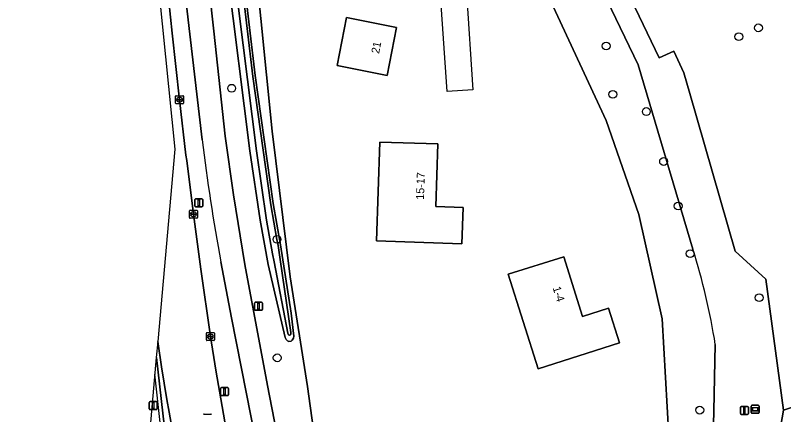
# Model space of a CAD drawing. Extents: x 159451 to 160664, y 388402 to 389723.
# Drawn here: x 159456.5 to 159552.4, y 389143.7 to 389193.6 of the extents above; entities that cross this region are included whole.
import ezdxf

# ---------------------------------------------------------------- set-up
doc = ezdxf.new("R2010")
doc.units = 0
for name, color, linetype in [('IMGEO_Afsluitpaal', 7, 'Continuous'), ('IMGEO_Berm_groen', 7, 'Continuous'), ('IMGEO_Boom', 7, 'Continuous'), ('IMGEO_Bouwland', 7, 'Continuous'), ('IMGEO_Fietspad_gesloten', 7, 'Continuous'), ('IMGEO_Grasland_overig', 7, 'Continuous'), ('IMGEO_Greppel_droge_sloot', 7, 'Continuous'), ('IMGEO_Groenvoorziening', 7, 'Continuous'), ('IMGEO_Hek', 7, 'Continuous'), ('IMGEO_Informatiebord', 7, 'Continuous'), ('IMGEO_Kolk', 7, 'Continuous'), ('IMGEO_Lichtmast', 7, 'Continuous'), ('IMGEO_Oever', 7, 'Continuous'), ('IMGEO_Pand', 7, 'Continuous'), ('IMGEO_Pand_nummerreeks', 7, 'Continuous'), ('IMGEO_Pand_vergunning_verleend', 7, 'Continuous'), ('IMGEO_Rijbaan_regionaal_gesloten', 7, 'Continuous'), ('IMGEO_Rioolput', 7, 'Continuous'), ('IMGEO_Voetpad_open', 7, 'Continuous')]:
    doc.layers.add(name, color=color, linetype=linetype)

msp = doc.modelspace()

# ---------------------------------------------------------------- linework, layer by layer
at = {"layer": 'IMGEO_Afsluitpaal'}
for p, q in [((159547.004, 389143.85), (159547.004, 389144.65)), ((159547.004, 389144.65), (159547.004, 389143.85)), ((159547.104, 389144.75), (159547.894, 389144.75)), ((159547.894, 389144.75), (159547.104, 389144.75)), ((159547.994, 389144.65), (159547.994, 389143.85)), ((159547.994, 389143.85), (159547.994, 389144.65)), ((159547.894, 389143.75), (159547.104, 389143.75)), ((159547.104, 389143.75), (159547.894, 389143.75))]:
    msp.add_line(p, q, dxfattribs=at)
msp.add_lwpolyline([(159547.424, 389144.625), (159547.574, 389144.625), (159547.574, 389143.875), (159547.424, 389143.875), (159547.424, 389144.625)], dxfattribs=at)
for centre, start, end in [((159547.104, 389144.65), 90, 180), ((159547.104, 389144.65), 90, 180), ((159547.894, 389144.65), 0, 90), ((159547.894, 389144.65), 360, 90), ((159547.104, 389143.85), 180, 270), ((159547.104, 389143.85), 180, 270), ((159547.894, 389143.85), 270, 0), ((159547.894, 389143.85), 270, 0)]:
    msp.add_arc(centre, 0.1, start, end, dxfattribs=at)
at = {"layer": 'IMGEO_Berm_groen'}
for points in [[(159479.81, 389178.066), (159478.244, 389191.231), (159476.688, 389204.954), (159476.115, 389210.723), (159473.293, 389238.955), (159471.683, 389255.143), (159470.151, 389272.51), (159468.609, 389291.384), (159467.063, 389310.472), (159465.649, 389329.916), (159464.342, 389348.5), (159462.508, 389376.402), (159461.071, 389403.687), (159459.294, 389436.93)], [(159475.213, 389199.409), (159476.055, 389191.357), (159476.981, 389183.062), (159477.784, 389176.125), (159477.869, 389175.45), (159478.713, 389168.759), (159479.637, 389161.877), (159480.832, 389153.482), (159481.503, 389149.299), (159483.264, 389139.262), (159485.702, 389125.061), (159486.085, 389122.792)], [(159489.673, 389123.332), (159487.529, 389135.114), (159485.311, 389146.532), (159483.459, 389155.81), (159482.145, 389162.815)], [(159474.251, 389152.87), (159474.073, 389150.873), (159474.122, 389150.878), (159477.483, 389121.203), (159479.117, 389121.427)], [(159479.49, 389121.919), (159477.882, 389131.561), (159476.254, 389140.727), (159475.679, 389144.041), (159475.404, 389145.63), (159474.719, 389149.681), (159474.251, 389152.87)]]:
    msp.add_lwpolyline(points, dxfattribs=at)
msp.add_arc((159698.001, 389203.668), 219.688, 186.6923, 190.71702, dxfattribs=at)
at = {"layer": 'IMGEO_Boom'}
for centre in [(159549.254, 389192.032), (159546.8, 389190.929), (159530.24, 389189.771), (159483.48, 389184.488), (159531.071, 389183.726), (159535.251, 389181.578), (159537.411, 389175.343), (159539.233, 389169.779), (159489.139, 389165.616), (159540.731, 389163.833), (159549.348, 389158.333), (159489.173, 389150.822), (159541.926, 389144.291)]:
    msp.add_circle(centre, 0.489, dxfattribs=at)
at = {"layer": 'IMGEO_Bouwland'}
msp.add_lwpolyline([(159486.712, 389292.863), (159536.847, 389188.304), (159538.67, 389189.107), (159539.945, 389186.409), (159540.689, 389183.824), (159546.355, 389164.126), (159550.196, 389160.656), (159552.375, 389144.269), (159583.383, 389154.602)], dxfattribs=at)
for points in [[(159487.441, 389272.575), (159480.836, 389288.81), (159478.228, 389288.738), (159479.211, 389271.897), (159488.551, 389179.124), (159490.78, 389160.929), (159492.959, 389147.253), (159495.943, 389125.547), (159496.063, 389124.735), (159496.335, 389123.276), (159496.729, 389122.189), (159497.183, 389121.597), (159498.11, 389121.139), (159499.541, 389121.106), (159518.516, 389121.775), (159539.156, 389122.203), (159538.081, 389141.023), (159537.243, 389155.693), (159534.303, 389168.702), (159530.224, 389180.456)], [(159504.064, 389192.091), (159502.892, 389186.087), (159496.658, 389187.324), (159497.826, 389193.308)], [(159509.239, 389177.532), (159508.962, 389169.711), (159512.369, 389169.587), (159512.206, 389165.051), (159501.559, 389165.416), (159501.991, 389177.773)], [(159518.017, 389161.253), (159524.936, 389163.454), (159527.305, 389155.997), (159530.546, 389157.029), (159531.919, 389152.7), (159521.761, 389149.463)]]:
    msp.add_lwpolyline(points, close=True, dxfattribs=at)
at = {"layer": 'IMGEO_Fietspad_gesloten'}
for points in [[(159461.071, 389403.687), (159462.508, 389376.402), (159464.342, 389348.5), (159465.649, 389329.916), (159467.063, 389310.472), (159468.609, 389291.384), (159470.151, 389272.51), (159471.683, 389255.143), (159473.293, 389238.955), (159476.115, 389210.723), (159476.688, 389204.954), (159478.244, 389191.231), (159479.81, 389178.066)], [(159482.145, 389162.815), (159483.459, 389155.81), (159485.311, 389146.532), (159487.529, 389135.114), (159489.673, 389123.332), (159492.885, 389123.261), (159492.482, 389125.078), (159491.057, 389131.504), (159487.963, 389147.366), (159485.138, 389162.462), (159483.697, 389171.161), (159482.691, 389178.486), (159481.255, 389191.613), (159479.595, 389206.774)]]:
    msp.add_lwpolyline(points, dxfattribs=at)
msp.add_arc((159698.001, 389203.668), 219.688, 186.6923, 190.71702, dxfattribs=at)
at = {"layer": 'IMGEO_Grasland_overig'}
for points in [[(159486.712, 389292.863), (159483.087, 389292.351), (159491.324, 389276.977), (159493.1, 389273.212), (159500, 389258.58), (159504.093, 389250), (159534.245, 389187.399), (159541.062, 389164.374)], [(159543.868, 389152.492), (159543.663, 389144.191), (159543.127, 389122.477), (159551.705, 389123.07), (159550.85, 389135.446), (159552.375, 389144.269), (159550.196, 389160.656), (159546.355, 389164.126), (159540.689, 389183.824), (159539.945, 389186.409), (159538.67, 389189.107), (159536.847, 389188.304), (159486.712, 389292.863)]]:
    msp.add_lwpolyline(points, dxfattribs=at)
msp.add_arc((159465.827, 389140.335), 78.982, 8.85455, 17.72, dxfattribs=at)
at = {"layer": 'IMGEO_Greppel_droge_sloot'}
msp.add_lwpolyline([(159483.778, 389198.834), (159486.574, 389176.685), (159487.854, 389168.014), (159488.602, 389163.826), (159488.797, 389162.797), (159490.487, 389153.895), (159490.538, 389153.785), (159490.596, 389153.695), (159490.701, 389153.64), (159490.759, 389153.652), (159490.843, 389153.709), (159490.882, 389153.795), (159490.884, 389153.895), (159490.866, 389154.004), (159489.544, 389163.12), (159489.298, 389164.837), (159489.139, 389165.616), (159488.368, 389169.95), (159486.114, 389185.938), (159483.986, 389203.971)], dxfattribs=at)
at = {"layer": 'IMGEO_Groenvoorziening'}
for points in [[(159471.882, 389288.893), (159473.199, 389272.868), (159474.73, 389255.582), (159476.315, 389239.166), (159479.167, 389211.269), (159479.595, 389206.774), (159481.255, 389191.613), (159482.691, 389178.486), (159483.697, 389171.161), (159485.138, 389162.462), (159487.963, 389147.366), (159491.057, 389131.504), (159492.482, 389125.078), (159495.943, 389125.547), (159492.959, 389147.253), (159490.78, 389160.929), (159488.551, 389179.124), (159479.211, 389271.897)], [(159541.062, 389164.374), (159534.245, 389187.399), (159504.093, 389250), (159500, 389258.58), (159493.1, 389273.212), (159487.441, 389272.575), (159530.224, 389180.456), (159534.303, 389168.702), (159537.243, 389155.693), (159538.081, 389141.023), (159539.156, 389122.203), (159543.127, 389122.477), (159543.663, 389144.191)], [(159484.285, 389204.106), (159486.412, 389186.084), (159488.663, 389170.113), (159489.602, 389164.953), (159490.896, 389156.395), (159491.245, 389153.512), (159491.194, 389153.27), (159491.057, 389153.021), (159490.9, 389152.917), (159490.624, 389152.875), (159490.458, 389152.949), (159490.295, 389153.124), (159490.153, 389153.348), (159488.037, 389162.469), (159487.05, 389167.999), (159485.767, 389176.684), (159482.97, 389198.843)], [(159583.383, 389154.602), (159552.375, 389144.269), (159550.85, 389135.446)], [(159543.663, 389144.191), (159543.868, 389152.492)]]:
    msp.add_lwpolyline(points, dxfattribs=at)
msp.add_arc((159465.827, 389140.335), 78.982, 8.85455, 17.72, dxfattribs=at)
at = {"layer": 'IMGEO_Hek'}
for points in [[(159552.375, 389144.269), (159583.383, 389154.602), (159594.464, 389157.944)], [(159474.61, 389142.37), (159473.885, 389148.761)]]:
    msp.add_lwpolyline(points, dxfattribs=at)
at = {"layer": 'IMGEO_Informatiebord'}
for p, q in [((159548.438, 389144.893), (159549.228, 389144.893)), ((159549.228, 389144.893), (159548.438, 389144.893)), ((159548.338, 389143.993), (159548.338, 389144.793)), ((159548.338, 389144.793), (159548.338, 389143.993)), ((159549.328, 389144.793), (159549.328, 389143.993)), ((159549.328, 389143.993), (159549.328, 389144.793)), ((159549.228, 389143.893), (159548.438, 389143.893)), ((159548.438, 389143.893), (159549.228, 389143.893))]:
    msp.add_line(p, q, dxfattribs=at)
for points in [[(159548.439, 389144.625), (159549.227, 389144.625), (159549.227, 389144.161), (159548.439, 389144.161), (159548.439, 389144.625)], [(159548.504, 389144.56), (159548.504, 389144.226), (159549.162, 389144.226), (159549.162, 389144.56), (159548.504, 389144.56)]]:
    msp.add_lwpolyline(points, dxfattribs=at)
for centre, start, end in [((159548.438, 389144.793), 90, 180), ((159548.438, 389144.793), 90, 180), ((159549.228, 389144.793), 0, 90), ((159549.228, 389144.793), 360, 90), ((159548.438, 389143.993), 180, 270), ((159548.438, 389143.993), 180, 270), ((159549.228, 389143.993), 270, 0), ((159549.228, 389143.993), 270, 0)]:
    msp.add_arc(centre, 0.1, start, end, dxfattribs=at)
at = {"layer": 'IMGEO_Kolk'}
for p, q in [((159476.48, 389182.636), (159476.48, 389183.488)), ((159476.555, 389183.562), (159477.407, 389183.562)), ((159476.968, 389183.342), (159476.993, 389183.342)), ((159477.481, 389183.488), (159477.481, 389182.636)), ((159477.407, 389182.562), (159476.555, 389182.562)), ((159476.739, 389183.056), (159476.739, 389183.068)), ((159477.177, 389183.019), (159476.779, 389183.019)), ((159476.782, 389183.105), (159477.18, 389183.105)), ((159476.991, 389182.782), (159476.966, 389182.782)), ((159477.223, 389183.068), (159477.223, 389183.056)), ((159478.212, 389168.333), (159478.212, 389169.185)), ((159478.287, 389169.259), (159479.139, 389169.259)), ((159478.7, 389169.039), (159478.725, 389169.039)), ((159479.213, 389169.185), (159479.213, 389168.333)), ((159479.139, 389168.259), (159478.287, 389168.259)), ((159478.471, 389168.753), (159478.471, 389168.765)), ((159478.909, 389168.716), (159478.511, 389168.716)), ((159478.514, 389168.802), (159478.912, 389168.802)), ((159478.723, 389168.479), (159478.698, 389168.479)), ((159478.955, 389168.765), (159478.955, 389168.753)), ((159480.331, 389153.056), (159480.331, 389153.908)), ((159480.406, 389153.982), (159481.258, 389153.982)), ((159480.633, 389153.525), (159481.031, 389153.525)), ((159480.819, 389153.762), (159480.844, 389153.762)), ((159481.332, 389153.908), (159481.332, 389153.056)), ((159481.258, 389152.982), (159480.406, 389152.982)), ((159480.59, 389153.476), (159480.59, 389153.488)), ((159481.028, 389153.439), (159480.63, 389153.439)), ((159480.842, 389153.202), (159480.817, 389153.202)), ((159481.074, 389153.488), (159481.074, 389153.476))]:
    msp.add_line(p, q, dxfattribs=at)
for points in [[(159476.48, 389182.636), (159476.48, 389183.488)], [(159476.555, 389183.562), (159477.407, 389183.562)], [(159477.481, 389183.488), (159477.481, 389182.636)], [(159477.407, 389182.562), (159476.555, 389182.562)], [(159478.212, 389168.333), (159478.212, 389169.185)], [(159478.287, 389169.259), (159479.139, 389169.259)], [(159479.213, 389169.185), (159479.213, 389168.333)], [(159479.139, 389168.259), (159478.287, 389168.259)], [(159480.331, 389153.056), (159480.331, 389153.908)], [(159480.406, 389153.982), (159481.258, 389153.982)], [(159481.332, 389153.908), (159481.332, 389153.056)], [(159481.258, 389152.982), (159480.406, 389152.982)]]:
    msp.add_lwpolyline(points, dxfattribs=at)
for centre, radius, start, end in [((159476.557, 389183.486), 0.0765, 91.55205, 178.44795), ((159476.557, 389183.486), 0.0765, 91.55205, 178.44795), ((159477.405, 389183.486), 0.0765, 1.55205, 88.44795), ((159477.405, 389183.486), 0.0765, 1.55205, 88.44795), ((159476.557, 389182.638), 0.0765, 181.55205, 268.44795), ((159476.557, 389182.638), 0.0765, 181.55205, 268.44795), ((159476.779, 389183.065), 0.0403, 85.87752, 175.75265), ((159476.776, 389183.055), 0.0366, 178.93798, 274.71019), ((159477.18, 389183.062), 0.043, 264.86636, 352.45326), ((159477.184, 389183.067), 0.0386, 1.73085, 96.63898), ((159477.405, 389182.638), 0.0765, 271.55205, 358.44795), ((159477.405, 389182.638), 0.0765, 271.55205, 358.44795), ((159478.289, 389169.183), 0.0765, 91.55205, 178.44795), ((159478.289, 389169.183), 0.0765, 91.55205, 178.44795), ((159479.137, 389169.183), 0.0765, 1.55205, 88.44795), ((159479.137, 389169.183), 0.0765, 1.55205, 88.44795), ((159478.289, 389168.335), 0.0765, 181.55205, 268.44795), ((159478.289, 389168.335), 0.0765, 181.55205, 268.44795), ((159478.511, 389168.762), 0.0403, 85.87752, 175.75265), ((159478.508, 389168.752), 0.0366, 178.93798, 274.71019), ((159478.912, 389168.759), 0.043, 264.86636, 352.45326), ((159478.916, 389168.764), 0.0386, 1.73085, 96.63898), ((159479.137, 389168.335), 0.0765, 271.55205, 358.44795), ((159479.137, 389168.335), 0.0765, 271.55205, 358.44795), ((159480.408, 389153.906), 0.0765, 91.55205, 178.44795), ((159480.408, 389153.906), 0.0765, 91.55205, 178.44795), ((159480.63, 389153.485), 0.0403, 85.87752, 175.75265), ((159481.035, 389153.487), 0.0386, 1.73085, 96.63898), ((159481.256, 389153.906), 0.0765, 1.55205, 88.44795), ((159481.256, 389153.906), 0.0765, 1.55205, 88.44795), ((159480.408, 389153.058), 0.0765, 181.55205, 268.44795), ((159480.408, 389153.058), 0.0765, 181.55205, 268.44795), ((159480.627, 389153.475), 0.0366, 178.93798, 274.71019), ((159481.031, 389153.482), 0.043, 264.86636, 352.45326), ((159481.256, 389153.058), 0.0765, 271.55205, 358.44795), ((159481.256, 389153.058), 0.0765, 271.55205, 358.44795)]:
    msp.add_arc(centre, radius, start, end, dxfattribs=at)
for centre, major_axis, ratio, start_param, end_param in [((159476.967, 389183.062), (-0.387, 0.002), 0.722429, 4.712389, 7.853982), ((159476.992, 389183.062), (-0.39, 0.002), 0.717154, 1.570796, 4.712389), ((159478.699, 389168.759), (-0.387, 0.002), 0.722429, 4.712389, 7.853982), ((159478.724, 389168.759), (-0.39, 0.002), 0.717154, 1.570796, 4.712389), ((159480.818, 389153.482), (-0.387, 0.002), 0.722429, 4.712389, 7.853982), ((159480.843, 389153.482), (-0.39, 0.002), 0.717154, 1.570796, 4.712389)]:
    msp.add_ellipse(centre, major_axis=major_axis, ratio=ratio, start_param=start_param, end_param=end_param, dxfattribs=at)
at = {"layer": 'IMGEO_Lichtmast'}
for p, q in [((159478.887, 389169.78), (159478.887, 389170.58)), ((159478.887, 389170.58), (159478.887, 389169.78)), ((159478.987, 389170.68), (159479.777, 389170.68)), ((159479.777, 389170.68), (159478.987, 389170.68)), ((159479.877, 389170.58), (159479.877, 389169.78)), ((159479.877, 389169.78), (159479.877, 389170.58)), ((159479.777, 389169.68), (159478.987, 389169.68)), ((159478.987, 389169.68), (159479.777, 389169.68)), ((159486.339, 389156.86), (159486.339, 389157.66)), ((159486.339, 389157.66), (159486.339, 389156.86)), ((159486.439, 389157.76), (159487.229, 389157.76)), ((159487.229, 389157.76), (159486.439, 389157.76)), ((159487.329, 389157.66), (159487.329, 389156.86)), ((159487.329, 389156.86), (159487.329, 389157.66)), ((159487.229, 389156.76), (159486.439, 389156.76)), ((159486.439, 389156.76), (159487.229, 389156.76)), ((159482.103, 389146.202), (159482.103, 389147.002)), ((159482.103, 389147.002), (159482.103, 389146.202)), ((159482.203, 389147.102), (159482.993, 389147.102)), ((159482.993, 389147.102), (159482.203, 389147.102)), ((159483.093, 389147.002), (159483.093, 389146.202)), ((159483.093, 389146.202), (159483.093, 389147.002)), ((159482.993, 389146.102), (159482.203, 389146.102)), ((159482.203, 389146.102), (159482.993, 389146.102)), ((159473.193, 389144.457), (159473.193, 389145.257)), ((159473.193, 389145.257), (159473.193, 389144.457)), ((159473.293, 389145.357), (159474.083, 389145.357)), ((159474.083, 389145.357), (159473.293, 389145.357)), ((159474.183, 389145.257), (159474.183, 389144.457)), ((159474.183, 389144.457), (159474.183, 389145.257)), ((159474.083, 389144.357), (159473.293, 389144.357)), ((159473.293, 389144.357), (159474.083, 389144.357))]:
    msp.add_line(p, q, dxfattribs=at)
for points in [[(159479.307, 389170.555), (159479.457, 389170.555), (159479.457, 389169.805), (159479.307, 389169.805), (159479.307, 389170.555)], [(159486.759, 389157.635), (159486.909, 389157.635), (159486.909, 389156.885), (159486.759, 389156.885), (159486.759, 389157.635)], [(159482.523, 389146.977), (159482.673, 389146.977), (159482.673, 389146.227), (159482.523, 389146.227), (159482.523, 389146.977)], [(159473.613, 389145.232), (159473.763, 389145.232), (159473.763, 389144.482), (159473.613, 389144.482), (159473.613, 389145.232)]]:
    msp.add_lwpolyline(points, dxfattribs=at)
for centre, start, end in [((159478.987, 389170.58), 90, 180), ((159478.987, 389170.58), 90, 180), ((159479.777, 389170.58), 0, 90), ((159479.777, 389170.58), 360, 90), ((159478.987, 389169.78), 180, 270), ((159478.987, 389169.78), 180, 270), ((159479.777, 389169.78), 270, 0), ((159479.777, 389169.78), 270, 0), ((159486.439, 389157.66), 90, 180), ((159486.439, 389157.66), 90, 180), ((159487.229, 389157.66), 0, 90), ((159487.229, 389157.66), 360, 90), ((159486.439, 389156.86), 180, 270), ((159486.439, 389156.86), 180, 270), ((159487.229, 389156.86), 270, 0), ((159487.229, 389156.86), 270, 0), ((159482.203, 389147.002), 90, 180), ((159482.203, 389147.002), 90, 180), ((159482.993, 389147.002), 0, 90), ((159482.993, 389147.002), 360, 90), ((159482.203, 389146.202), 180, 270), ((159482.203, 389146.202), 180, 270), ((159482.993, 389146.202), 270, 0), ((159482.993, 389146.202), 270, 0), ((159473.293, 389145.257), 90, 180), ((159473.293, 389145.257), 90, 180), ((159474.083, 389145.257), 0, 90), ((159474.083, 389145.257), 360, 90), ((159473.293, 389144.457), 180, 270), ((159473.293, 389144.457), 180, 270), ((159474.083, 389144.457), 270, 0), ((159474.083, 389144.457), 270, 0)]:
    msp.add_arc(centre, 0.1, start, end, dxfattribs=at)
at = {"layer": 'IMGEO_Oever'}
for points in [[(159482.97, 389198.843), (159485.767, 389176.684), (159487.05, 389167.999), (159488.037, 389162.469), (159490.153, 389153.348), (159490.295, 389153.124), (159490.458, 389152.949), (159490.624, 389152.875), (159490.9, 389152.917), (159491.057, 389153.021), (159491.194, 389153.27), (159491.245, 389153.512), (159490.896, 389156.395), (159489.602, 389164.953), (159488.663, 389170.113), (159486.412, 389186.084), (159484.285, 389204.106)], [(159483.986, 389203.971), (159486.114, 389185.938), (159488.368, 389169.95), (159489.139, 389165.616), (159489.298, 389164.837), (159489.544, 389163.12), (159490.866, 389154.004), (159490.884, 389153.895), (159490.882, 389153.795), (159490.843, 389153.709), (159490.759, 389153.652), (159490.701, 389153.64), (159490.596, 389153.695), (159490.538, 389153.785), (159490.487, 389153.895), (159488.797, 389162.797), (159488.602, 389163.826), (159487.854, 389168.014), (159486.574, 389176.685), (159483.778, 389198.834)]]:
    msp.add_lwpolyline(points, dxfattribs=at)
at = {"layer": 'IMGEO_Pand'}
for points in [[(159504.064, 389192.091), (159497.826, 389193.308), (159496.658, 389187.324), (159502.892, 389186.087)], [(159512.369, 389169.587), (159508.962, 389169.711), (159509.239, 389177.532), (159501.991, 389177.773), (159501.559, 389165.416), (159512.206, 389165.051)], [(159524.936, 389163.454), (159518.017, 389161.253), (159521.761, 389149.463), (159531.919, 389152.7), (159530.546, 389157.029), (159527.305, 389155.997)]]:
    msp.add_lwpolyline(points, close=True, dxfattribs=at)
at = {"layer": 'IMGEO_Pand_vergunning_verleend'}
msp.add_lwpolyline([(159509.568, 389196.173), (159512.785, 389196.387), (159513.592, 389184.311), (159510.374, 389184.096)], close=True, dxfattribs=at)
at = {"layer": 'IMGEO_Rijbaan_regionaal_gesloten'}
for points in [[(159456.481, 389421.006), (159461.772, 389332.122), (159463.341, 389305.754), (159468.546, 389254.372), (159476.395, 389176.888), (159474.251, 389152.87)], [(159474.251, 389152.87), (159474.719, 389149.681), (159475.404, 389145.63), (159475.679, 389144.041), (159476.254, 389140.727), (159477.882, 389131.561), (159479.49, 389121.919), (159479.844, 389118.477), (159486.47, 389119.358), (159486.661, 389119.402), (159486.085, 389122.792), (159485.702, 389125.061), (159483.264, 389139.262), (159481.503, 389149.299), (159480.832, 389153.482), (159479.637, 389161.877), (159478.713, 389168.759), (159477.869, 389175.45), (159477.784, 389176.125), (159476.981, 389183.062), (159476.055, 389191.357), (159475.213, 389199.409)]]:
    msp.add_lwpolyline(points, dxfattribs=at)
at = {"layer": 'IMGEO_Rioolput'}
msp.add_line((159480.036, 389143.8), (159480.888, 389143.8), dxfattribs=at)
msp.add_lwpolyline([(159480.036, 389143.8), (159480.888, 389143.8)], dxfattribs=at)
for centre, start, end in [((159480.038, 389143.724), 91.55205, 178.44795), ((159480.038, 389143.724), 91.55205, 178.44795), ((159480.886, 389143.724), 1.55205, 88.44795), ((159480.886, 389143.724), 1.55205, 88.44795)]:
    msp.add_arc(centre, 0.0765, start, end, dxfattribs=at)
at = {"layer": 'IMGEO_Voetpad_open'}
for points in [[(159474.073, 389150.873), (159472.96, 389138.4), (159475.835, 389117.929), (159479.844, 389118.477), (159479.49, 389121.919)], [(159479.117, 389121.427), (159477.483, 389121.203), (159474.122, 389150.878), (159474.073, 389150.873)]]:
    msp.add_lwpolyline(points, dxfattribs=at)

# ---------------------------------------------------------------- texts
at = {"layer": 'IMGEO_Pand_nummerreeks'}
for s, rotation, p in [('21', 78.95358, (159501.884, 389188.752)), ('15-17', 87.97194, (159507.491, 389170.561)), ('1-4', 287.62397, (159523.547, 389159.568))]:
    msp.add_text(s, height=1, rotation=rotation, dxfattribs=at).set_placement(p)

doc.saveas('drawing.dxf')
